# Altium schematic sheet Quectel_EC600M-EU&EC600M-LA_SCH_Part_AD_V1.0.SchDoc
size A1
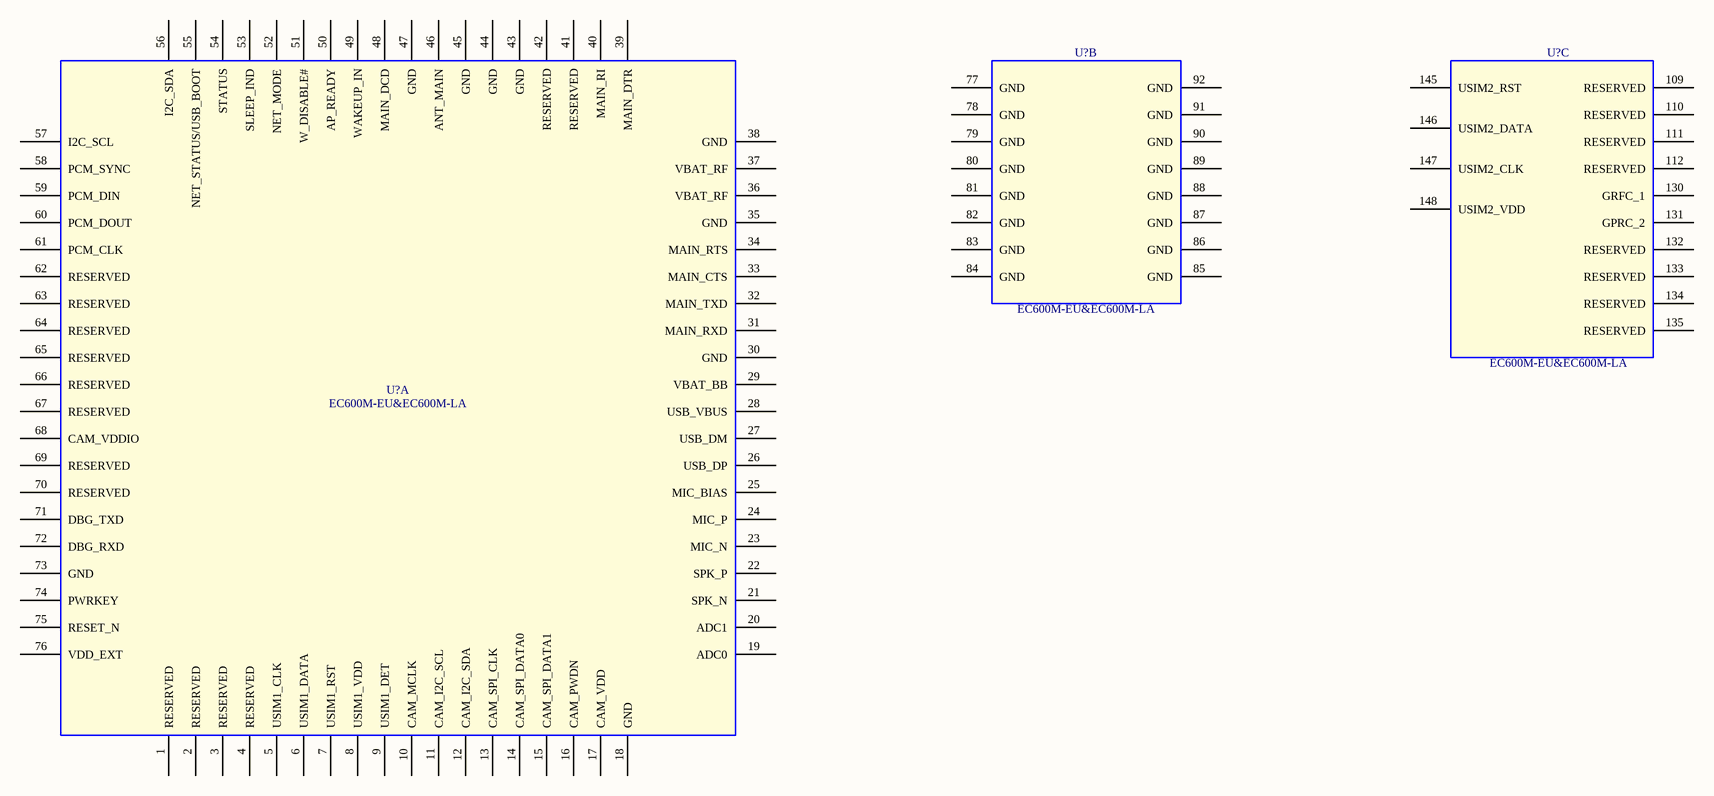
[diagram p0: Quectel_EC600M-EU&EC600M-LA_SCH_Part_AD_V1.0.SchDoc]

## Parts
(Parts that share a designator on the sheet are numbered #1, #2 ... from top to bottom, then left to right.)
U?#1  EC600M-EU&EC600M-LA  [EC600M-EU_EC600M-LA]  (part B of 3)
U?#2  EC600M-EU&EC600M-LA  [EC600M-EU_EC600M-LA]  (part C of 3)
U?#3  EC600M-EU&EC600M-LA  [EC600M-EU_EC600M-LA]  (part A of 3)

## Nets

Not connected (* = marked no-connect by the designer): U?#1 77(GND) 78(GND) 79(GND) 80(GND) 81(GND) 82(GND) 83(GND) 84(GND) 85(GND) 86(GND) 87(GND) 88(GND) 89(GND) 90(GND) 91(GND) 92(GND); U?#2 109(RESERVED) 110(RESERVED) 111(RESERVED) 112(RESERVED) 130(GRFC_1) 131(GPRC_2) 132(RESERVED) 133(RESERVED) 134(RESERVED) 135(RESERVED) 145(USIM2_RST) 146(USIM2_DATA) 147(USIM2_CLK) 148(USIM2_VDD); U?#3 1(RESERVED) 2(RESERVED) 3(RESERVED) 4(RESERVED) 5(USIM1_CLK) 6(USIM1_DATA) 7(USIM1_RST) 8(USIM1_VDD) 9(USIM1_DET) 10(CAM_MCLK) 11(CAM_I2C_SCL) 12(CAM_I2C_SDA) 13(CAM_SPI_CLK) 14(CAM_SPI_DATA0) 15(CAM_SPI_DATA1) 16(CAM_PWDN) 17(CAM_VDD) 18(GND) 19(ADC0) 20(ADC1) 21(SPK_N) 22(SPK_P) 23(MIC_N) 24(MIC_P) 25(MIC_BIAS) 26(USB_DP) 27(USB_DM) 28(USB_VBUS) 29(VBAT_BB) 30(GND) 31(MAIN_RXD) 32(MAIN_TXD) 33(MAIN_CTS) 34(MAIN_RTS) 35(GND) 36(VBAT_RF) 37(VBAT_RF) 38(GND) 39(MAIN_DTR) 40(MAIN_RI) 41(RESERVED) 42(RESERVED) 43(GND) 44(GND) 45(GND) 46(ANT_MAIN) 47(GND) 48(MAIN_DCD) 49(WAKEUP_IN) 50(AP_READY) 51(W_DISABLE#) 52(NET_MODE) 53(SLEEP_IND) 54(STATUS) 55(NET_STATUS/USB_BOOT) 56(I2C_SDA) 57(I2C_SCL) 58(PCM_SYNC) 59(PCM_DIN) 60(PCM_DOUT) 61(PCM_CLK) 62(RESERVED) 63(RESERVED) 64(RESERVED) 65(RESERVED) 66(RESERVED) 67(RESERVED) 68(CAM_VDDIO) 69(RESERVED) 70(RESERVED) 71(DBG_TXD) 72(DBG_RXD) 73(GND) 74(PWRKEY) 75(RESET_N) 76(VDD_EXT)

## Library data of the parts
U?#1-U?#3 = EC600M-EU_EC600M-LA: EC600M-EU&EC600M-LA Module 106PIN 21.9x22.9mm H2.4mm RO; Manufacturer: Quectel; Geometry.Height: 2.4mm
